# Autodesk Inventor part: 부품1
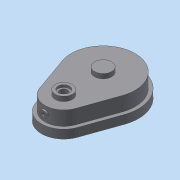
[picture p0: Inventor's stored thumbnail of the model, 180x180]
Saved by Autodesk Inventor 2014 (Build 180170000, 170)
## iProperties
Created: 2024-05
Part Number: 부품1
Material: 일반
Document SubType Name: Modeling
Designer: dg
Density: 1 g/cm^3
Appearance: 기본값
Author: dg
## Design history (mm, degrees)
sketch "스케치1"
  geometry: L1 (-58.454, -20.667)-(-36.77, -82); L2 (58.454, -20.667)-(36.77, -82); A1 r 62 centre (0, 0) between (-58.454, -20.667) and (58.454, -20.667); A2 r 39 centre (0, -69) between (-36.77, -82) and (36.77, -82); 1 further point
  constraints: 4 end point, 4 point on circle, 4 tangent, 2 centre point, 1 coincident, 1 vertical alignment
  dimensions: "d0" = 124 diameter of A1; "d1" = 78 diameter of A2; "d2" = 69 distance of A2.centre point (0, 0)
extrude "돌출1" new body sketch "스케치1" distance "d3" = 15; taper "d4" = 0 deg
sketch "스케치2"
  geometry: L1 (52.797, -18.667)-(31.113, -80); L2 (-52.797, -18.667)-(-31.113, -80); A1 r 62 centre (0, 0) between (58.454, -20.667) and (-58.454, -20.667) reference; A2 r 39 centre (0, -69) between (-36.77, -82) and (36.77, -82) reference; A3 r 56 centre (0, 0) between (52.797, -18.667) and (-52.797, -18.667); A4 r 33 centre (0, -69) between (-31.113, -80) and (31.113, -80)
  constraints: 4 end point, 4 point on circle, 4 tangent, 2 centre point, 2 coincident
  dimensions: "d5" = 112 diameter of A3; "d6" = 66 diameter of A4
extrude "돌출2" join sketch "스케치2" distance "d7" = 25; taper "d8" = 0 deg
sketch "스케치3"
  geometry: C1 r 15 at (0, 0); A1 r 56 centre (0, 0) between (52.797, -18.667) and (-52.797, -18.667) reference
  constraints: 1 centre point, 1 coincident
  dimensions: "d9" = 30 diameter of C1
extrude "돌출3" join sketch "스케치3" distance "d10" = 8; taper "d11" = 0 deg
sketch "스케치4"
  geometry: C1 r 15 at (0, -69); A1 r 33 centre (0, -69) between (-31.113, -80) and (31.113, -80) reference
  constraints: 1 centre point, 1 coincident
  dimensions: "d12" = 30 diameter of C1
extrude "돌출4" join sketch "스케치4" distance "d13" = 8; taper "d14" = 0 deg
sketch "스케치5"
  geometry: L1 (48.083, -17)-(26.399, -78.333); L2 (-48.083, -17)-(-26.399, -78.333); A1 r 39 centre (0, -69) between (-36.77, -82) and (36.77, -82) reference; A2 r 62 centre (0, 0) between (58.454, -20.667) and (-58.454, -20.667) reference; A3 r 51 centre (0, 0) between (48.083, -17) and (-48.083, -17); A4 r 28 centre (0, -69) between (-26.399, -78.333) and (26.399, -78.333)
  constraints: 4 end point, 4 point on circle, 4 tangent, 2 centre point, 2 coincident
  dimensions: "d15" = 102 diameter of A3; "d16" = 56 diameter of A4
extrude "돌출5" cut sketch "스케치5" distance "d17" = 35; taper "d18" = 0 deg
sketch "스케치6"
  geometry: C1 r 14 at (0, 0); A1 r 51 centre (0, 0) between (48.083, -17) and (-48.083, -17) reference
  constraints: 1 centre point, 1 coincident
  dimensions: "d19" = 28 diameter of C1
extrude "돌출6" join sketch "스케치6" distance "d20" = 8; taper "d21" = 0 deg
sketch "스케치7"
  geometry: C1 r 14 at (0, -69); A1 r 28 centre (0, -69) between (-26.399, -78.333) and (26.399, -78.333) reference
  constraints: 1 centre point, 1 coincident
  dimensions: "d22" = 28 diameter of C1
extrude "돌출7" join sketch "스케치7" distance "d23" = 8; taper "d24" = 0 deg
hole "구멍1" diameter "d27" = 14; stored, may be unused: countersink angle "d31" = 90 deg, drill point angle "d33" = 0 deg; dims "d25" = 10, "d26" = 10, "d28" = 6, "d29" = 20, "d30" = 4.2, "d32" = 8
hole "구멍2" diameter "d36" = 14; stored, may be unused: countersink angle "d40" = 90 deg, drill point angle "d42" = 0 deg; dims "d34" = 10, "d35" = 10, "d37" = 6, "d38" = 20, "d39" = 4.2, "d41" = 10
sketch "스케치8"
  geometry: L1 (-18.667, 15)-(-18.667, 15) reference; L2 (-18.667, 15)-(-18.667, 40) reference; L3 (-18.667, 40)-(-18.667, 40) reference; L4 (-18.667, 15)-(-18.667, 40) reference; L5 (7, 27)-(-7, 27) reference; L6 (-7, 37)-(7, 37) reference; L7 (0, 39.309)-(4, 37); L8 (-4, 37)-(0, 39.309); L9 (0, 39.309)-(0, 37); 1 further point
  constraints: 6 end point, 2 point on line, 1 equal length, 1 midpoint, 1 perpendicular, 1 vertical alignment
  dimensions: "d45" = 8 distance of L7.end L8.start; "d46" = 120 deg angle of L8 L7
revolve "회전1" sketch "스케치8" stored, may be unused: angle "d47" = 90 deg
node "작업 평면1"
sketch "스케치9"
  geometry: L1 (56, 40)-(-56, 40) reference; L2 (62, 0)-(-62, 0) reference; C1 r 6 at (0, 28); 6 further points
  constraints: 1 centre point, 1 midpoint, 1 vertical alignment
  dimensions: "d49" = 12 diameter of C1; "d50" = 28 distance from line of L2 C1.centre
extrude "돌출8" join sketch "스케치9" stored distance "d51" = 8; taper "d52" = 0 deg
hole "구멍3" diameter "d55" = 5.188; stored, may be unused: countersink angle "d59" = 90 deg, drill point angle "d61" = 0 deg; dims "d56" = 100, "d57" = 7, "d58" = 2, "d60" = 10, "d64" = 10, "d65" = 10
node "작업 평면2"
sketch "스케치10"
  geometry: L1 (31.113, 40)-(-31.113, 40) reference; L2 (36.77, 0)-(-36.77, 0) reference; C1 r 6 at (0, 28); 2 further points
  constraints: 1 centre point, 1 midpoint, 1 vertical alignment
  dimensions: "d63" = 12 diameter of C1; "d66" = 28 distance from line of L2 C1.centre
extrude "돌출9" join sketch "스케치10" stored distance "d67" = 8; taper "d68" = 0 deg
hole "구멍4" diameter "d71" = 5.188; stored, may be unused: countersink angle "d75" = 90 deg, drill point angle "d77" = 0 deg; dims "d72" = 15, "d73" = 7, "d74" = 2, "d76" = 10, "d78" = 10, "d79" = 10
node "솔리드1"
node "투영된 루프1"
node "투영된 루프2"
other parameters: "d48" = 59, "d62" = -105
